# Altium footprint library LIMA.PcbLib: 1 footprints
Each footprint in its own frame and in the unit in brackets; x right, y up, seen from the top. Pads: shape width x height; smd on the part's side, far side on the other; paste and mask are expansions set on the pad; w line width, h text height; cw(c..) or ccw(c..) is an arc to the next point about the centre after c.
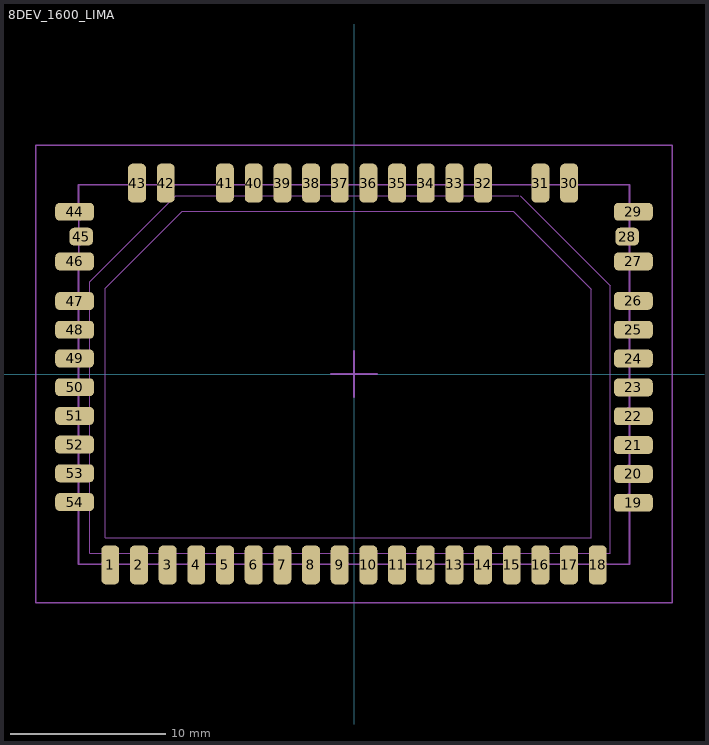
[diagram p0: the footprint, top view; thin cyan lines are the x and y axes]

## 8DEV_1600_LIMA [mm]
pads (54):
  rrect50% 1.15x2.5 smd: 1(-15.7,-12.3) 2(-13.853,-12.3) 3(-12.006,-12.3) 4(-10.159,-12.3) 5(-8.312,-12.3) 6(-6.465,-12.3) 7(-4.618,-12.3) 8(-2.771,-12.3) 9(-0.924,-12.3) 10(0.924,-12.3) 11(2.771,-12.3) 12(4.618,-12.3) 13(6.465,-12.3) 14(8.312,-12.3) 15(10.159,-12.3) 16(12.006,-12.3) 17(13.853,-12.3) 18(15.7,-12.3) 30(13.86,12.3) 31(12.01,12.3) 32(8.315,12.3) 33(6.468,12.3) 34(4.621,12.3) 35(2.774,12.3) 36(0.926,12.3) 37(-0.921,12.3) 38(-2.768,12.3) 39(-4.615,12.3) 40(-6.462,12.3) 41(-8.321,12.3) 42(-12.13,12.3) 43(-13.98,12.3)
  rrect50% 2.5x1.15 smd: 19(18,-8.3) 20(18,-6.441) 21(18,-4.582) 22(18,-2.723) 23(18,-0.864) 24(18,0.994) 25(18,2.853) 26(18,4.712) 27(18,7.25) 29(18,10.45) 44(-18,10.45) 46(-18,7.25) 47(-18,4.7) 48(-18,2.85) 49(-18,1) 50(-18,-0.85) 51(-18,-2.7) 52(-18,-4.55) 53(-18,-6.4) 54(-18,-8.25)
  rrect50% 1.5x1.15 smd: 28(17.6,8.85) 45(-17.575,8.85)
Top Paste:
  drawing of 54 lines, arcs and shapes, not listed
Mechanical 14:
  lines w0.05: 10.6,11.5 -11.475,11.5 -17.025,5.95 -17.025,-11.55 16.525,-11.55 16.525,5.7 10.725,11.5 ; -16.025,-10.55 15.275,-10.55 15.275,5.475 10.25,10.5 -11.061,10.5 -16.025,5.536 -16.025,-10.55
  lines w0.1: -17.751,6.714 -17.749,5.245 cw(c-17.825,4.7) -17.75,4.155 -17.749,3.395 cw(c-17.825,2.85) -17.75,2.305 -17.749,1.545 cw(c-17.825,1) -17.75,0.455 -17.749,-0.305 cw(c-17.825,-0.85) -17.75,-1.395 -17.749,-2.155 cw(c-17.825,-2.7) -17.75,-3.245 -17.749,-4.005 cw(c-17.825,-4.55) -17.75,-5.095 -17.749,-5.855 cw(c-17.825,-6.4) -17.75,-6.945 -17.749,-7.705 cw(c-17.825,-8.25) -17.75,-8.795 -17.75,-12.25 -16.256,-12.25 ; -17.75,10.986 -17.75,12.2 -14.516,12.2 ccw(c-13.98,12.3) -13.444,12.2 -12.666,12.2 ccw(c-12.13,12.3) -11.594,12.2 -8.857,12.2 ccw(c-8.321,12.3) -7.784,12.2 ; -17.726,8.314 -17.725,7.786 cw(c-17.825,7.25) -17.725,6.714 ; -17.726,9.914 -17.725,9.386 cw(c-17.825,8.85) -17.725,8.314 ; -17.725,10.986 cw(c-17.825,10.45) -17.725,9.914 ; -16.256,-12.249 cw(c-15.716,-12.35) -15.175,-12.249 -14.407,-12.249 cw(c-13.867,-12.35) -13.326,-12.249 -12.559,-12.249 cw(c-12.018,-12.35) -11.477,-12.249 -10.71,-12.249 cw(c-10.169,-12.35) -9.628,-12.249 -8.861,-12.249 cw(c-8.32,-12.35) -7.78,-12.249 -7.012,-12.249 cw(c-6.471,-12.35) -5.931,-12.249 -5.163,-12.249 cw(c-4.623,-12.35) -4.082,-12.249 -3.314,-12.249 cw(c-2.774,-12.35) -2.233,-12.249 -1.466,-12.249 cw(c-0.925,-12.35) -0.384,-12.249 0.383,-12.249 cw(c0.924,-12.35) 1.464,-12.249 2.232,-12.249 cw(c2.773,-12.35) 3.313,-12.249 4.081,-12.249 cw(c4.621,-12.35) 5.162,-12.249 5.93,-12.249 cw(c6.47,-12.35) 7.011,-12.249 7.778,-12.249 cw(c8.319,-12.35) 8.86,-12.249 9.627,-12.249 cw(c10.168,-12.35) 10.709,-12.249 11.476,-12.249 cw(c12.017,-12.35) 12.557,-12.249 13.325,-12.249 cw(c13.866,-12.35) 14.406,-12.249 15.174,-12.249 cw(c15.714,-12.35) 16.255,-12.249 17.75,-12.25 17.752,-8.791 cw(c17.85,-8.25) 17.75,-7.709 17.75,-6.941 ; -7.785,12.2 -7.008,12.2 ccw(c-6.472,12.3) -5.935,12.2 ; -5.936,12.2 -5.159,12.2 ccw(c-4.623,12.3) -4.086,12.2 ; -4.088,12.2 -3.31,12.2 ccw(c-2.774,12.3) -2.238,12.2 ; -2.239,12.2 -1.461,12.2 ccw(c-0.925,12.3) -0.389,12.2 ; -0.39,12.2 0.388,12.2 ccw(c0.924,12.3) 1.46,12.2 ; 1.459,12.2 2.237,12.2 ccw(c2.773,12.3) 3.309,12.2 ; 3.308,12.2 4.085,12.2 ccw(c4.622,12.3) 5.158,12.2 5.934,12.2 ccw(c6.471,12.3) 7.007,12.2 ; 7.006,12.2 7.783,12.2 ccw(c8.319,12.3) 8.856,12.2 11.474,12.2 ccw(c12.01,12.3) 12.546,12.2 13.324,12.2 ccw(c13.86,12.3) 14.396,12.2 17.75,12.2 17.75,10.986 ccw(c17.85,10.45) 17.75,9.914 17.75,9.386 ccw(c17.85,8.85) 17.75,8.314 17.75,7.786 ccw(c17.85,7.25) 17.75,6.714 17.75,5.241 ccw(c17.85,4.7) 17.752,4.159 ; 17.75,-5.091 17.75,-5.859 ccw(c17.85,-6.4) 17.752,-6.941 ; 17.75,-3.241 17.75,-4.009 ccw(c17.85,-4.55) 17.752,-5.091 ; 17.75,-1.391 17.75,-2.159 ccw(c17.85,-2.7) 17.752,-3.241 ; 17.75,0.459 17.75,-0.309 ccw(c17.85,-0.85) 17.752,-1.391 ; 17.75,2.309 17.75,1.541 ccw(c17.85,1) 17.752,0.459 ; 17.75,4.159 17.75,3.391 ccw(c17.85,2.85) 17.752,2.309
  text ".designator" at -7.547,2.691 h1.5
  text ".comment" at -7.497,1.066 h1.12
Mechanical 15:
  lines w0.1: 0,-1.5 0,1.5 0,0 ; 0,0 1.5,0 -1.5,0 0,0 ; -20.5,-14.75 20.5,-14.75 20.5,14.75 -20.5,14.75 -20.5,-14.75
3D body "8dev-1600_0004.step": height 3.6, standoff -0.32, extent -17.75,-12.25 17.75,12.2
